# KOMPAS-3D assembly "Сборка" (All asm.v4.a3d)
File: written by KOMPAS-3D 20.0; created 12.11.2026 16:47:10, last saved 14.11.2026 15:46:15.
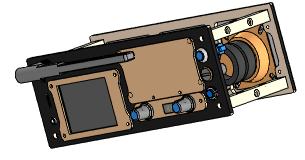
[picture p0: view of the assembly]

Document properties: Полное имя файла: D:\myProjects\Progect_esp32\box_compas\All asm.v4.a3d

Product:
- Part/product: Сборка
    Масса: 3.09374
  - Component [assembly]: Сборка  | Масса: 1.48065; source file: сборки компонентов\Back_Panel_Сборка_v4.a3d
  - Component [assembly]: Сборка  | Масса: 1.6131; source file: корпус\корпус v1 asm.a3d

Referenced files in D:\myProjects\Progect_esp32\box_compas\корпус\: корпус v1 asm.a3d
Referenced files in D:\myProjects\Progect_esp32\box_compas\сборки компонентов\: Back_Panel_Сборка_v4.a3d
